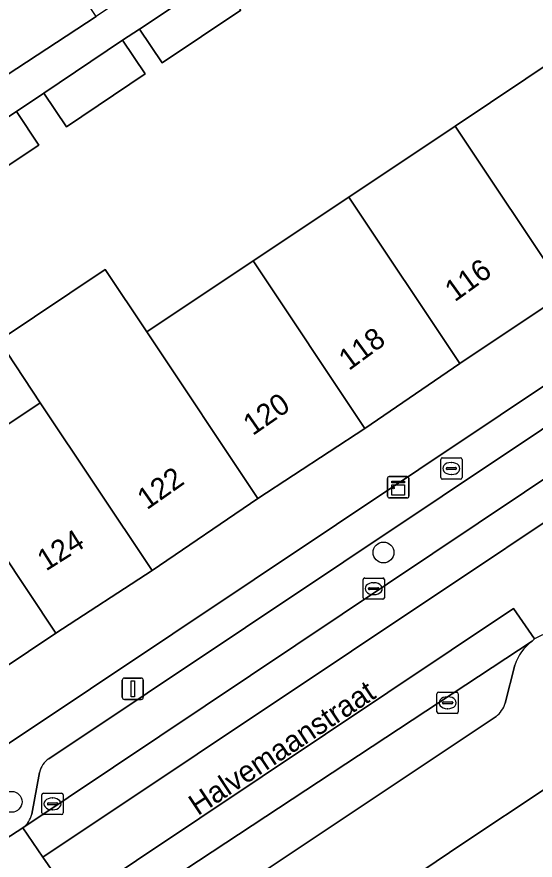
# Model space of a CAD drawing. Extents: x 158352 to 159489, y 383828 to 384603.
# Drawn here: x 158756.34 to 158780.66, y 384168.53 to 384208.09 of the extents above; entities that cross this region are included whole.
import ezdxf

# ---------------------------------------------------------------- set-up
doc = ezdxf.new("R2010")
doc.units = 0
for name, color, linetype in [('IMGEO_Boom', 7, 'Continuous'), ('IMGEO_Brandkraan', 7, 'Continuous'), ('IMGEO_Erf', 7, 'Continuous'), ('IMGEO_Kast', 7, 'Continuous'), ('IMGEO_Kolk', 7, 'Continuous'), ('IMGEO_Lichtmast', 7, 'Continuous'), ('IMGEO_Openbare_ruimte_label', 7, 'Continuous'), ('IMGEO_Pand', 7, 'Continuous'), ('IMGEO_Pand_nummerreeks', 7, 'Continuous'), ('IMGEO_Parkeervlak_open', 7, 'Continuous'), ('IMGEO_Rijbaan_lokaal_gesloten', 7, 'Continuous'), ('IMGEO_Rijbaan_lokaal_open', 7, 'Continuous'), ('IMGEO_Voetpad_open', 7, 'Continuous')]:
    doc.layers.add(name, color=color, linetype=linetype)

msp = doc.modelspace()

# ---------------------------------------------------------------- linework, layer by layer
at = {"layer": 'IMGEO_Boom'}
for centre in [(158773.543, 384182.963), (158756.089, 384171.265)]:
    msp.add_circle(centre, 0.489, dxfattribs=at)
at = {"layer": 'IMGEO_Brandkraan'}
for p, q in [((158776.228, 384186.476), (158776.228, 384187.328)), ((158776.303, 384187.402), (158777.155, 384187.402)), ((158777.229, 384187.328), (158777.229, 384186.476)), ((158776.487, 384186.896), (158776.487, 384186.908)), ((158776.925, 384186.859), (158776.527, 384186.859)), ((158776.53, 384186.945), (158776.928, 384186.945)), ((158776.716, 384187.182), (158776.741, 384187.182)), ((158776.971, 384186.908), (158776.971, 384186.896)), ((158776.739, 384186.622), (158776.714, 384186.622)), ((158777.155, 384186.402), (158776.303, 384186.402))]:
    msp.add_line(p, q, dxfattribs=at)
for points in [[(158776.228, 384186.476), (158776.228, 384187.328)], [(158776.303, 384187.402), (158777.155, 384187.402)], [(158777.229, 384187.328), (158777.229, 384186.476)], [(158777.155, 384186.402), (158776.303, 384186.402)]]:
    msp.add_lwpolyline(points, dxfattribs=at)
for centre, radius, start, end in [((158776.305, 384187.326), 0.0765, 91.552, 178.448), ((158776.305, 384187.326), 0.0765, 91.552, 178.448), ((158777.153, 384187.326), 0.0765, 1.552, 88.448), ((158777.153, 384187.326), 0.0765, 1.552, 88.448), ((158776.527, 384186.905), 0.0403, 85.8775, 175.7526), ((158776.524, 384186.895), 0.0366, 178.938, 274.7102), ((158776.928, 384186.902), 0.043, 264.8664, 352.4533), ((158776.932, 384186.907), 0.0386, 1.7309, 96.639), ((158776.305, 384186.478), 0.0765, 181.552, 268.448), ((158776.305, 384186.478), 0.0765, 181.552, 268.448), ((158777.153, 384186.478), 0.0765, 271.552, 358.448), ((158777.153, 384186.478), 0.0765, 271.552, 358.448)]:
    msp.add_arc(centre, radius, start, end, dxfattribs=at)
for centre, major_axis, ratio, start_param, end_param in [((158776.715, 384186.902), (-0.387, 0.002), 0.722429, 4.712389, 7.853982), ((158776.74, 384186.902), (-0.39, 0.002), 0.717154, 1.570796, 4.712389)]:
    msp.add_ellipse(centre, major_axis=major_axis, ratio=ratio, start_param=start_param, end_param=end_param, dxfattribs=at)
at = {"layer": 'IMGEO_Erf'}
msp.add_lwpolyline([(158766.842, 384208.399), (158763.158, 384205.927), (158762.099, 384207.505), (158761.301, 384206.989), (158762.358, 384205.41), (158758.66, 384202.935), (158757.603, 384204.514), (158756.312, 384203.657), (158757.363, 384202.077), (158753.675, 384199.623), (158752.622, 384201.206), (158751.342, 384200.289), (158752.394, 384198.707), (158748.69, 384196.244), (158747.638, 384197.826), (158746.844, 384197.289), (158747.9, 384195.71), (158744.228, 384193.253), (158743.172, 384194.832), (158738.549, 384191.749), (158752.1, 384171.43), (158802.113, 384204.829), (158788.594, 384225.155)], dxfattribs=at)
for points in [[(158762.429, 384193.318), (158767.425, 384196.648), (158771.909, 384199.638), (158776.904, 384202.967), (158781.884, 384206.291), (158786.38, 384209.294), (158792.699, 384213.514), (158795.295, 384209.606), (158794.187, 384208.841), (158796.785, 384204.942), (158791.593, 384201.478), (158787.135, 384198.42), (158782.117, 384195.154), (158777.123, 384191.822), (158772.673, 384188.781), (158767.646, 384185.498), (158762.68, 384182.121), (158758.17, 384179.174), (158752.974, 384175.706), (158747.751, 384183.533), (158752.949, 384186.999), (158757.435, 384189.983), (158755.483, 384192.906), (158760.477, 384196.241)], [(158773.289, 384161.59), (158777.931, 384164.695), (158777.49, 384165.354), (158777.582, 384165.415), (158781.31, 384167.91), (158782.733, 384165.783), (158783.739, 384166.456), (158788.571, 384169.689), (158787.198, 384171.886), (158785.32, 384174.656), (158777.222, 384169.281), (158754.637, 384154.044), (158747.356, 384149.809), (158750.204, 384144.913), (158754.924, 384148.07), (158756.059, 384148.83), (158755.051, 384150.336), (158758.65, 384152.744), (158759.088, 384152.089), (158759.288, 384152.223), (158760.269, 384152.879), (158763.821, 384155.256), (158768.555, 384158.422)]]:
    msp.add_lwpolyline(points, close=True, dxfattribs=at)
at = {"layer": 'IMGEO_Kast'}
for p, q in [((158773.734, 384185.597), (158773.734, 384186.438)), ((158773.734, 384186.438), (158773.734, 384185.597)), ((158773.809, 384186.522), (158774.65, 384186.522)), ((158774.65, 384186.522), (158773.809, 384186.522)), ((158774.734, 384186.447), (158774.734, 384185.606)), ((158774.734, 384185.606), (158774.734, 384186.447)), ((158774.659, 384185.522), (158773.818, 384185.522)), ((158773.818, 384185.522), (158774.659, 384185.522))]:
    msp.add_line(p, q, dxfattribs=at)
for points in [[(158773.929, 384186.312), (158774.529, 384186.312), (158774.529, 384186.227), (158773.929, 384186.227), (158773.929, 384186.312)], [(158773.929, 384186.137), (158774.529, 384186.137), (158774.529, 384185.648), (158773.929, 384185.648), (158773.929, 384186.137)]]:
    msp.add_lwpolyline(points, dxfattribs=at)
msp.add_circle((158774.013, 384185.986), 0.0377, dxfattribs=at)
for centre, start, end in [((158773.812, 384186.444), 92.4484, 184.2845), ((158773.812, 384186.444), 92.4484, 184.2845), ((158774.656, 384186.444), 2.4484, 94.2845), ((158774.656, 384186.444), 2.4484, 94.2845), ((158773.812, 384185.6), 182.4484, 274.2845), ((158773.812, 384185.6), 182.4484, 274.2845), ((158774.656, 384185.6), 272.4484, 4.2845), ((158774.656, 384185.6), 272.4484, 4.2845)]:
    msp.add_arc(centre, 0.0779, start, end, dxfattribs=at)
at = {"layer": 'IMGEO_Kolk'}
for p, q in [((158772.584, 384180.839), (158772.584, 384181.691)), ((158772.659, 384181.765), (158773.511, 384181.765)), ((158773.585, 384181.691), (158773.585, 384180.839)), ((158772.886, 384181.308), (158773.284, 384181.308)), ((158773.072, 384181.545), (158773.097, 384181.545)), ((158772.843, 384181.259), (158772.843, 384181.271)), ((158773.281, 384181.222), (158772.883, 384181.222)), ((158773.095, 384180.985), (158773.07, 384180.985)), ((158773.327, 384181.271), (158773.327, 384181.259)), ((158773.511, 384180.765), (158772.659, 384180.765)), ((158776.05, 384175.485), (158776.05, 384176.337)), ((158776.125, 384176.411), (158776.977, 384176.411)), ((158776.538, 384176.191), (158776.563, 384176.191)), ((158777.051, 384176.337), (158777.051, 384175.485)), ((158776.309, 384175.905), (158776.309, 384175.917)), ((158776.747, 384175.868), (158776.349, 384175.868)), ((158776.352, 384175.954), (158776.75, 384175.954)), ((158776.793, 384175.917), (158776.793, 384175.905)), ((158776.977, 384175.411), (158776.125, 384175.411)), ((158776.561, 384175.631), (158776.536, 384175.631)), ((158757.507, 384170.743), (158757.507, 384171.595)), ((158757.582, 384171.669), (158758.434, 384171.669)), ((158757.995, 384171.449), (158758.02, 384171.449)), ((158758.508, 384171.595), (158758.508, 384170.743)), ((158757.766, 384171.163), (158757.766, 384171.175)), ((158758.204, 384171.126), (158757.806, 384171.126)), ((158757.809, 384171.212), (158758.207, 384171.212)), ((158758.25, 384171.175), (158758.25, 384171.163)), ((158758.434, 384170.669), (158757.582, 384170.669)), ((158758.018, 384170.889), (158757.993, 384170.889))]:
    msp.add_line(p, q, dxfattribs=at)
for points in [[(158772.584, 384180.839), (158772.584, 384181.691)], [(158772.659, 384181.765), (158773.511, 384181.765)], [(158773.585, 384181.691), (158773.585, 384180.839)], [(158773.511, 384180.765), (158772.659, 384180.765)], [(158776.05, 384175.485), (158776.05, 384176.337)], [(158776.125, 384176.411), (158776.977, 384176.411)], [(158777.051, 384176.337), (158777.051, 384175.485)], [(158776.977, 384175.411), (158776.125, 384175.411)], [(158757.507, 384170.743), (158757.507, 384171.595)], [(158757.582, 384171.669), (158758.434, 384171.669)], [(158758.508, 384171.595), (158758.508, 384170.743)], [(158758.434, 384170.669), (158757.582, 384170.669)]]:
    msp.add_lwpolyline(points, dxfattribs=at)
for centre, radius, start, end in [((158772.661, 384181.689), 0.0765, 91.552, 178.448), ((158772.661, 384181.689), 0.0765, 91.552, 178.448), ((158773.509, 384181.689), 0.0765, 1.552, 88.448), ((158773.509, 384181.689), 0.0765, 1.552, 88.448), ((158772.883, 384181.268), 0.0403, 85.8775, 175.7526), ((158773.288, 384181.27), 0.0386, 1.7309, 96.639), ((158772.88, 384181.258), 0.0366, 178.938, 274.7102), ((158773.284, 384181.265), 0.043, 264.8664, 352.4533), ((158772.661, 384180.841), 0.0765, 181.552, 268.448), ((158772.661, 384180.841), 0.0765, 181.552, 268.448), ((158773.509, 384180.841), 0.0765, 271.552, 358.448), ((158773.509, 384180.841), 0.0765, 271.552, 358.448), ((158776.127, 384176.335), 0.0765, 91.552, 178.448), ((158776.127, 384176.335), 0.0765, 91.552, 178.448), ((158776.975, 384176.335), 0.0765, 1.552, 88.448), ((158776.975, 384176.335), 0.0765, 1.552, 88.448), ((158776.349, 384175.914), 0.0403, 85.8775, 175.7526), ((158776.346, 384175.904), 0.0366, 178.938, 274.7102), ((158776.75, 384175.911), 0.043, 264.8664, 352.4533), ((158776.754, 384175.916), 0.0386, 1.7309, 96.639), ((158776.127, 384175.487), 0.0765, 181.552, 268.448), ((158776.127, 384175.487), 0.0765, 181.552, 268.448), ((158776.975, 384175.487), 0.0765, 271.552, 358.448), ((158776.975, 384175.487), 0.0765, 271.552, 358.448), ((158757.584, 384171.593), 0.0765, 91.552, 178.448), ((158757.584, 384171.593), 0.0765, 91.552, 178.448), ((158758.432, 384171.593), 0.0765, 1.552, 88.448), ((158758.432, 384171.593), 0.0765, 1.552, 88.448), ((158757.806, 384171.172), 0.0403, 85.8775, 175.7526), ((158757.803, 384171.162), 0.0366, 178.938, 274.7102), ((158758.207, 384171.169), 0.043, 264.8664, 352.4533), ((158758.211, 384171.174), 0.0386, 1.7309, 96.639), ((158757.584, 384170.745), 0.0765, 181.552, 268.448), ((158757.584, 384170.745), 0.0765, 181.552, 268.448), ((158758.432, 384170.745), 0.0765, 271.552, 358.448), ((158758.432, 384170.745), 0.0765, 271.552, 358.448)]:
    msp.add_arc(centre, radius, start, end, dxfattribs=at)
for centre, major_axis, ratio, start_param, end_param in [((158773.071, 384181.265), (-0.387, 0.002), 0.722429, 4.712389, 7.853982), ((158773.096, 384181.265), (-0.39, 0.002), 0.717154, 1.570796, 4.712389), ((158776.537, 384175.911), (-0.387, 0.002), 0.722429, 4.712389, 7.853982), ((158776.562, 384175.911), (-0.39, 0.002), 0.717154, 1.570796, 4.712389), ((158757.994, 384171.169), (-0.387, 0.002), 0.722429, 4.712389, 7.853982), ((158758.019, 384171.169), (-0.39, 0.002), 0.717154, 1.570796, 4.712389)]:
    msp.add_ellipse(centre, major_axis=major_axis, ratio=ratio, start_param=start_param, end_param=end_param, dxfattribs=at)
at = {"layer": 'IMGEO_Lichtmast'}
for p, q in [((158761.28, 384176.17), (158761.28, 384176.97)), ((158761.28, 384176.97), (158761.28, 384176.17)), ((158761.38, 384177.07), (158762.17, 384177.07)), ((158762.17, 384177.07), (158761.38, 384177.07)), ((158762.27, 384176.97), (158762.27, 384176.17)), ((158762.27, 384176.17), (158762.27, 384176.97)), ((158762.17, 384176.07), (158761.38, 384176.07)), ((158761.38, 384176.07), (158762.17, 384176.07))]:
    msp.add_line(p, q, dxfattribs=at)
msp.add_lwpolyline([(158761.7, 384176.945), (158761.85, 384176.945), (158761.85, 384176.195), (158761.7, 384176.195), (158761.7, 384176.945)], dxfattribs=at)
for centre, start, end in [((158761.38, 384176.97), 90, 180), ((158761.38, 384176.97), 90, 180), ((158762.17, 384176.97), 0, 90), ((158762.17, 384176.97), 360, 90), ((158761.38, 384176.17), 180, 270), ((158761.38, 384176.17), 180, 270), ((158762.17, 384176.17), 270, 0), ((158762.17, 384176.17), 270, 0)]:
    msp.add_arc(centre, 0.1, start, end, dxfattribs=at)
at = {"layer": 'IMGEO_Pand'}
for points in [[(158763.158, 384205.927), (158766.842, 384208.399), (158765.784, 384209.977), (158762.099, 384207.505)], [(158758.66, 384202.935), (158762.358, 384205.41), (158761.301, 384206.989), (158757.603, 384204.514)], [(158776.904, 384202.967), (158782.117, 384195.154), (158787.135, 384198.42), (158781.884, 384206.291)], [(158753.675, 384199.623), (158757.363, 384202.077), (158756.312, 384203.657), (158752.622, 384201.206)], [(158776.904, 384202.967), (158771.909, 384199.638), (158777.123, 384191.822), (158782.117, 384195.154)], [(158772.673, 384188.781), (158777.123, 384191.822), (158771.909, 384199.638), (158767.425, 384196.648)], [(158767.646, 384185.498), (158772.673, 384188.781), (158767.425, 384196.648), (158762.429, 384193.318)], [(158762.429, 384193.318), (158760.477, 384196.241), (158755.483, 384192.906), (158757.435, 384189.983), (158762.68, 384182.121), (158767.646, 384185.498)], [(158762.68, 384182.121), (158757.435, 384189.983), (158752.949, 384186.999), (158758.17, 384179.174)], [(158752.949, 384186.999), (158747.751, 384183.533), (158752.974, 384175.706), (158758.17, 384179.174)]]:
    msp.add_lwpolyline(points, close=True, dxfattribs=at)
at = {"layer": 'IMGEO_Parkeervlak_open'}
for points in [[(158745.185, 384229.466), (158741.472, 384226.964), (158755.874, 384205.363), (158760.063, 384208.099), (158745.402, 384230.033)], [(158756.613, 384170.048), (158784.422, 384188.633), (158795.826, 384196.626), (158802.34, 384200.987), (158801.626, 384200.892), (158800.21, 384201.209)], [(158799.425, 384201.034), (158757.838, 384173.287)], [(158780.514, 384178.796), (158759.872, 384165.217), (158756.455, 384162.969), (158757.707, 384161.186), (158762.82, 384164.587), (158766.3, 384166.915), (158778.824, 384175.261)], [(158779.26, 384175.887), (158779.711, 384177.675)], [(158757.401, 384172.648), (158757.038, 384170.692)]]:
    msp.add_lwpolyline(points, dxfattribs=at)
for centre, radius, start, end in [((158781.819, 384177.013), 2.21, 126.2037, 162.5664), ((158777.925, 384176.352), 1.414, 309.4901, 340.7966), ((158758.432, 384172.412), 1.058, 124.1674, 167.0977), ((158755.982, 384170.927), 1.082, 305.6814, 347.4739)]:
    msp.add_arc(centre, radius, start, end, dxfattribs=at)
at = {"layer": 'IMGEO_Rijbaan_lokaal_gesloten'}
for points in [[(158801.066, 384197.693), (158804.21, 384199.782), (158803.043, 384201.515), (158802.34, 384200.987), (158795.826, 384196.626), (158784.422, 384188.633), (158756.613, 384170.048), (158757.561, 384168.674)], [(158780.514, 384178.796), (158780.635, 384178.907), (158779.647, 384180.327), (158759.023, 384166.554), (158759.872, 384165.217)]]:
    msp.add_lwpolyline(points, close=True, dxfattribs=at)
at = {"layer": 'IMGEO_Rijbaan_lokaal_open'}
for points in [[(158833.556, 384216.278), (158832.123, 384218.384), (158824.254, 384213.149), (158819.204, 384209.77), (158818.226, 384211.198), (158818.138, 384211.137), (158816.531, 384210.036), (158803.043, 384201.515), (158804.21, 384199.782), (158801.066, 384197.693), (158757.561, 384168.674), (158759.023, 384166.554), (158779.647, 384180.327), (158780.635, 384178.907)], [(158753.215, 384162.703), (158754.1, 384161.357), (158756.455, 384162.969), (158759.872, 384165.217), (158759.023, 384166.554), (158757.561, 384168.674), (158756.613, 384170.048), (158755.775, 384169.498)]]:
    msp.add_lwpolyline(points, dxfattribs=at)
msp.add_arc((158783.223, 384174.381), 5.214, 25.2002, 119.7651, dxfattribs=at)
at = {"layer": 'IMGEO_Voetpad_open'}
for points in [[(158747.348, 384238.972), (158751.24, 384241.602), (158769.384, 384214.37), (158765.045, 384211.446), (158760.063, 384208.099), (158755.874, 384205.363), (158741.472, 384226.964), (158745.185, 384229.466)], [(158751.552, 384208.904), (158752.505, 384207.489), (158754.615, 384204.311), (158753.032, 384203.26), (158737.694, 384193.032), (158738.549, 384191.749), (158743.172, 384194.832), (158746.844, 384197.289), (158747.638, 384197.826), (158751.342, 384200.289), (158752.622, 384201.206), (158756.312, 384203.657), (158757.603, 384204.514), (158761.301, 384206.989), (158762.099, 384207.505), (158765.784, 384209.977)], [(158803.252, 384209.588), (158801.917, 384208.691), (158802.113, 384204.829), (158752.1, 384171.43), (158751.279, 384168.67)], [(158757.838, 384173.287), (158799.425, 384201.034)], [(158780.635, 384178.907), (158780.514, 384178.796)], [(158779.711, 384177.675), (158779.26, 384175.887)], [(158746.068, 384149.06), (158747.356, 384149.809), (158754.637, 384154.044), (158777.222, 384169.281), (158785.32, 384174.656), (158788.151, 384176.288), (158787.941, 384176.601)], [(158778.824, 384175.261), (158766.3, 384166.915), (158768.085, 384164.229), (158764.575, 384161.944), (158762.82, 384164.587), (158757.707, 384161.186), (158752.738, 384157.847), (158748.663, 384155.332), (158750.151, 384152.773), (158747.404, 384151.165), (158745.988, 384153.697), (158745.105, 384155.259), (158744.935, 384155.56), (158742.681, 384154.246), (158740.575, 384153.025), (158740.457, 384152.957), (158738.971, 384152.091)], [(158757.038, 384170.692), (158757.401, 384172.648)], [(158755.775, 384169.498), (158756.613, 384170.048)]]:
    msp.add_lwpolyline(points, dxfattribs=at)
for centre, radius, start, end in [((158783.223, 384174.381), 5.214, 25.2002, 119.7651), ((158781.819, 384177.013), 2.21, 126.2037, 162.5664), ((158777.925, 384176.352), 1.414, 309.4901, 340.7966), ((158758.432, 384172.412), 1.058, 124.1674, 167.0977), ((158755.982, 384170.927), 1.082, 305.6814, 347.4739)]:
    msp.add_arc(centre, radius, start, end, dxfattribs=at)

# ---------------------------------------------------------------- texts
at = {"layer": 'IMGEO_Openbare_ruimte_label'}
msp.add_text('Halvemaanstraat', height=1, rotation=33.5788, dxfattribs=at).set_placement((158764.83, 384170.589))
at = {"layer": 'IMGEO_Pand_nummerreeks'}
for s, rotation, p in [('116', 35.8463, (158776.888, 384194.693)), ('118', 36.3132, (158771.916, 384191.465)), ('120', 34.7037, (158767.404, 384188.419)), ('122', 35.0822, (158762.44, 384184.937)), ('124', 32.237, (158757.702, 384182.066))]:
    msp.add_text(s, height=1, rotation=rotation, dxfattribs=at).set_placement(p)

doc.saveas('drawing.dxf')
